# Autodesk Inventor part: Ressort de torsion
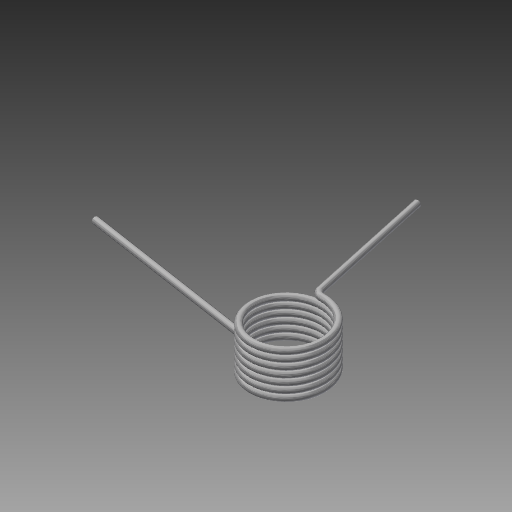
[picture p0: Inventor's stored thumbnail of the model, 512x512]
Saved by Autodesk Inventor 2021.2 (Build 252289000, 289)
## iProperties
CustomPartVersion: 1
Created: 2018-06
Part Number: Ressort de torsion
Material: Steel
Document SubType Name: Modeling
Designer: Fabian Perrée
Density: 1 g/cm^3
Appearance: Steel
Author: Fabian Perrée
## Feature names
1. Main Coil(R)
2. Bras de fonctionnement droit (droite)
3. Bras de fonctionnement droit axial (droite)
4. Bras de fonctionnement d'accrochage (droite)
5. Bras de fonctionnement d'accrochage interne (droite)
6. Bras de support droit (droit)
7. Bras de support droit axial (droite)
8. Bras de support d'accrochage (droite)
9. Bras de support d'accrochage interne (droite)
10. Main Coil(L)
11. StraightWorkingArm(L)
12. Bras de fonctionnement droit axial (gauche)
13. Bras de fonctionnement d'accrochage (gauche)
14. Bras de fonctionnement d'accrochage interne (gauche)
15. Bras de support droit (gauche)
16. Bras de support droit axial (gauche)
17. Bras de support d'accrochage (gauche)
18. Bras de support d'accrochage interne (gauche)
## Parameters: da_d = 0.5 mm, da_D2 = 5 mm, da_ni = 67.58776 mm, da_t = 0.525 mm, Not_rightdir = 0, da_r1 = 0.5 mm, Lr2 = 15 mm, da_r2 = 0.5 mm, const_zero = 0, d0 = 0.125 mm, d1 = 2.75 mm, d2 = 0.525 mm, d4 = 67.58776 mm, d5 = 0, d6 = 90 deg, d7 = 90 deg, d8 = 0, d9 = 0, d10 = 0.5 mm, d11 = 0, d13 = 0.5 mm, d14 = 0, d15 = 0.5 mm, d17 = 0, d19 = 0, d20 = 0.5 mm, d22 = 0, d28 = 0.525 mm, d30 = 67.58776 mm, d31 = 0, d32 = 90 deg, d33 = 90 deg, d34 = 0, d35 = 0, d36 = 0.5 mm, d37 = 0, d39 = 0.5 mm, d40 = 0, d41 = 0.5 mm, d43 = 0, d45 = 0, d46 = 0.5 mm, d48 = 0, leftWorkType = 0, leftSupportType = 0, d54 = 90 deg, d56 = 0.5 mm, d57 = 10.25 mm, d58 = 0, d59 = 0 mm, d60 = 0, da_Lr2 = 15 mm, d63 = 90 deg, d64 = 0.5 mm, d65 = 15.25 mm, d66 = 0, Is_w_HardEnd = 0, Is_s_HardEnd = 0, d67 = 0 mm, d69 = 0, d78 = 90 deg, d79 = 0.5 mm, d80 = 10.25 mm, d81 = 0, d82 = 0 mm, d84 = 0, d85 = 90 deg, d86 = 0.5 mm, d87 = 15.25 mm, d88 = 0, d89 = 0 mm, d91 = 0, d101 = 15 mm, d102 = 6 mm, d104 = 6 mm, d105 = 15 mm, d106 = 5 mm, d108 = 5 mm, d109 = 15 mm, d110 = 5 mm, d112 = 5 mm, d113 = 15 mm, d114 = 6 mm, d116 = 6 mm, d117 = 15 mm, d119 = 15 mm, Is_s_Internal = 0, Is_w_Internal = 0, d120 = 0, d121 = 0, d122 = 0, d123 = 0, d124 = 0, d125 = 0, d126 = 0, d127 = 0, d128 = 0, d129 = 0, d130 = 0, d131 = 0, d132 = 0, d133 = 0, d134 = 0, d135 = 0, d136 = 0, d137 = 0
